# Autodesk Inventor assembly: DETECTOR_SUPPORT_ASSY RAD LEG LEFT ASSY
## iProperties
Shininess: 64.0
Length Units: 11272
Angle Units: 11279
Time Units: 11290
Mass Units: 11286
Length Display Precision: 3
Angle Display Precision: 2
Compacted: True
Part Number: DETECTOR_SUPPORT_ASSY RAD LEG LEFT ASSY
Document SubType Name: Assembly
Created: 2004-08
Designer: John Blackburn
Manufacturer: Standard
Standards Organization: Custom
Density: 0.0
Volumn: 0.0
Area: 0.0
PropertySet Name: Model Information
Control State: 0
Master: False
Checked Out: False
Author: John Blackburn
